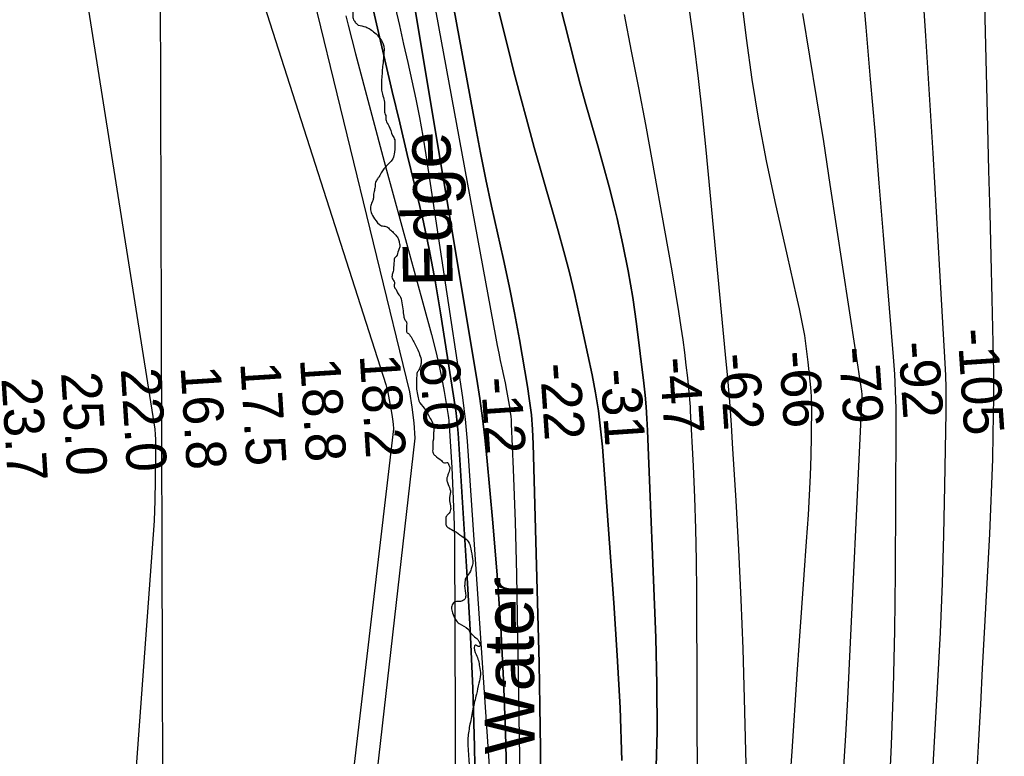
# Model space of a CAD drawing. Extents: x 3392644 to 3430565, y 576657 to 602123.
# Drawn here: x 3401788 to 3403434, y 588397 to 589627 of the extents above; entities that cross this region are included whole.
import ezdxf

# ---------------------------------------------------------------- set-up
doc = ezdxf.new("R2010")
doc.units = 0
for name, color, linetype in [('V-GRID-MAJR', 7, 'Continuous'), ('V-RIVR-EDGE', 7, 'Continuous'), ('V-RIVR-IDEN', 7, 'Continuous'), ('V-RIVR-RANG', 7, 'Continuous'), ('V-TOPO-DPTH', 7, 'Continuous'), ('V-TOPO-MAJR', 7, 'Continuous'), ('V-TOPO-MINR', 7, 'Continuous'), ('V-TOPO-WATR', 7, 'Continuous')]:
    doc.layers.add(name, color=color, linetype=linetype)

msp = doc.modelspace()

# ---------------------------------------------------------------- linework, layer by layer
at = {"layer": 'V-GRID-MAJR'}
msp.add_spline([(3402048.7, 582063.5), (3402028.4, 588122.7), (3402008.1, 594183.8), (3401987.8, 600244.9), (3401987.8, 600246.8)], degree=3, dxfattribs=at)
at = {"layer": 'V-RIVR-EDGE'}
for points in [[(3402225.6, 590211.5), (3402227.3, 590192.8), (3402229.7, 590176.3), (3402233.2, 590164.3), (3402236.4, 590151.2), (3402235.6, 590140), (3402236.3, 590123), (3402238, 590104.4), (3402239.7, 590087.8), (3402240.4, 590076.9), (3402241.1, 590060.7), (3402243.5, 590045.5), (3402245.6, 590032.1), (3402251.9, 590012.4), (3402259.9, 589993.3), (3402277.1, 589951), (3402284.5, 589928.8), (3402288.6, 589913.2), (3402293.5, 589897.4), (3402297.4, 589878.7), (3402301.2, 589857.2), (3402304.3, 589837.4), (3402303.2, 589822.7), (3402304.6, 589810), (3402308.1, 589790.6), (3402310.1, 589773.7), (3402314, 589761.3), (3402317.1, 589752.5), (3402320.3, 589740.9), (3402323.1, 589729.9), (3402325.2, 589722.5), (3402328.3, 589714.4), (3402332.5, 589705.2), (3402337.4, 589697.5), (3402337.4, 589693.9), (3402336.7, 589679.9), (3402336, 589670), (3402336, 589667.5), (3402336, 589664.7), (3402337.3, 589659.4), (3402338.7, 589655.2), (3402342.6, 589649.5), (3402345.1, 589645.3), (3402345.1, 589641.8), (3402345, 589634.7), (3402345, 589631.2), (3402346.4, 589627.3), (3402349.6, 589622.4), (3402353.8, 589618.5)], [(3402353.8, 589618.5), (3402366.5, 589615.3), (3402374.2, 589611.4), (3402381.6, 589605.7), (3402390, 589596.6), (3402395, 589588.4), (3402397.1, 589581.4), (3402397, 589574), (3402395.9, 589558.5), (3402394.5, 589546.5), (3402393.8, 589537), (3402393, 589512.3), (3402394.4, 589502.8), (3402397.5, 589492.2), (3402397.9, 589481.3), (3402398.2, 589473.2), (3402400.3, 589465.1), (3402400.6, 589459.1), (3402405.2, 589450.3), (3402411.5, 589434.1), (3402415, 589426.7), (3402415.3, 589418.2), (3402414.2, 589403), (3402410.3, 589392.8), (3402404, 589386.2), (3402398, 589379.5), (3402393.7, 589373.5), (3402389.1, 589365.4), (3402386.3, 589361.5), (3402383.1, 589355.6), (3402382.4, 589350.3), (3402381, 589342.2), (3402379.5, 589334.1), (3402379.2, 589328.4), (3402377.4, 589322.8), (3402375.6, 589318.9), (3402374.6, 589314.7), (3402375.6, 589305.5), (3402381.5, 589295), (3402392.8, 589283.3), (3402397, 589282.6), (3402403, 589280.8), (3402405.8, 589278.3), (3402411.1, 589273.4), (3402416.7, 589267.4), (3402420.9, 589261.7), (3402422.7, 589255), (3402423.4, 589248), (3402421.2, 589242), (3402417.7, 589232.1), (3402414.9, 589229.3), (3402414.1, 589225.8), (3402413.4, 589216.6), (3402412.3, 589206.8), (3402410.6, 589199.7), (3402410.6, 589195.9), (3402414.1, 589190.2), (3402414.8, 589187.4), (3402414, 589181.8), (3402417.2, 589176.5), (3402419.7, 589171.2), (3402424.6, 589164.1), (3402427.4, 589151.4), (3402429.4, 589137.7), (3402430.1, 589132.4), (3402432.2, 589126), (3402435, 589121.5), (3402435, 589116.9), (3402434.7, 589109.1), (3402434.6, 589106.3), (3402437.8, 589103.1), (3402443.4, 589095.4), (3402452.5, 589078.4), (3402456.7, 589068.2), (3402459.2, 589056.9), (3402458.5, 589050.6), (3402455.3, 589042.5), (3402452.8, 589038.2), (3402451.7, 589029.8), (3402451.3, 589013.2), (3402453.1, 589001.2), (3402455.5, 588991), (3402464.3, 588978.3), (3402474.5, 588961.4), (3402479.4, 588951.5), (3402480.4, 588942.7), (3402480, 588936), (3402480, 588928.6), (3402479.3, 588925.1), (3402478.9, 588923.3), (3402478.6, 588919.8), (3402478.6, 588911.7), (3402479.2, 588903.2), (3402482.4, 588899.3), (3402493, 588890.9), (3402500, 588887), (3402503.5, 588887.7), (3402504.9, 588884.8), (3402507, 588880.2), (3402506.7, 588875.3), (3402503.8, 588866.9), (3402502.4, 588862.3), (3402502.4, 588857.4), (3402504.1, 588851), (3402508, 588840.4), (3402507.6, 588834.4), (3402506.9, 588832), (3402506.5, 588826.7), (3402508.3, 588815.1), (3402507.9, 588807), (3402505.8, 588803.1), (3402501.9, 588798.9), (3402500.5, 588796), (3402500.5, 588789), (3402501.1, 588783), (3402505.4, 588778.4), (3402514.9, 588773.1), (3402527.2, 588764.6), (3402536.3, 588757.9), (3402541.2, 588748), (3402544.4, 588730.7), (3402545, 588716.3), (3402544, 588713.5), (3402541.5, 588706.4), (3402534.4, 588695.9), (3402533, 588692.7), (3402532.3, 588688.1), (3402531.9, 588681.8), (3402533.6, 588664.9), (3402532.2, 588659.2), (3402530.1, 588657.8), (3402526.6, 588656.1), (3402520.9, 588655.7), (3402516, 588655.1), (3402511, 588650.1), (3402510, 588645.9), (3402511.7, 588636.7), (3402516.6, 588625.5), (3402522.9, 588618.7), (3402537.7, 588609.5), (3402541.6, 588603.2), (3402555.3, 588590.1), (3402557.7, 588583.4), (3402557.4, 588581), (3402555.3, 588580.3), (3402549.3, 588582.7), (3402548.6, 588581.7), (3402551.4, 588566.9), (3402556.9, 588546.8), (3402558.3, 588533.4), (3402555.8, 588519.3), (3402551.5, 588500.6), (3402545.8, 588476.3), (3402540.8, 588450.6), (3402537.3, 588427.7), (3402537.6, 588409.4), (3402540.3, 588376.6), (3402543.8, 588353.7), (3402545.9, 588337.8), (3402545.8, 588329.4), (3402544.4, 588315.6), (3402545.1, 588298), (3402545.7, 588281.1), (3402547.8, 588258.2), (3402551.9, 588229.3), (3402553.3, 588209.6), (3402552.9, 588188.4), (3402549.7, 588179.6), (3402546.1, 588169.4), (3402540.8, 588162.7), (3402533.8, 588150.8), (3402529.9, 588147.3), (3402526, 588140.9), (3402522.4, 588130), (3402519.2, 588120.1), (3402514.6, 588114.5), (3402506.2, 588106.8), (3402488.2, 588098.7), (3402471.9, 588090), (3402440.6, 588078.8), (3402422.2, 588075.3), (3402415.9, 588073.5), (3402398.2, 588064.8), (3402386.6, 588057), (3402370.4, 588047.9), (3402356.2, 588038.8), (3402348.1, 588034.6), (3402339.3, 588028.6), (3402333.3, 588024.1), (3402331.2, 588019.5), (3402331.5, 588014.9), (3402332.5, 588000.1), (3402332.5, 587991.6), (3402329, 587984.2), (3402322.6, 587974.4), (3402313.8, 587963.8), (3402308.8, 587958.9), (3402306, 587955.8), (3402304.2, 587950.1), (3402303.9, 587945.2), (3402305.2, 587935), (3402309.8, 587926.5), (3402319.3, 587917), (3402329.5, 587902.8), (3402335.8, 587884.2), (3402342.1, 587862.3), (3402345.9, 587842.2), (3402353.9, 587818.9), (3402358.5, 587809.4), (3402369.7, 587790.7), (3402379.9, 587780.1), (3402387.3, 587770.2), (3402388.7, 587763.5), (3402389, 587754.3), (3402390, 587743.4), (3402392.1, 587734.6), (3402398.5, 587723), (3402409, 587712), (3402420.3, 587707.4), (3402430.5, 587701.4), (3402445.2, 587685.8), (3402460.3, 587664), (3402481.8, 587636.8), (3402490.5, 587630.1), (3402492.3, 587626.5), (3402492.3, 587618.1), (3402491.9, 587599.4), (3402491.9, 587595.5), (3402491.9, 587590.2), (3402495, 587583.2), (3402501.3, 587577.2), (3402510.1, 587565.9), (3402515.7, 587553.9), (3402518.5, 587544), (3402518.5, 587531.7), (3402519.5, 587529.2), (3402523.4, 587523.2), (3402528.3, 587508.7), (3402533.9, 587486.5), (3402537.7, 587460.8), (3402539, 587431.9), (3402536.9, 587417.1), (3402532.3, 587408.7), (3402524.9, 587399.9), (3402517.4, 587390), (3402513.5, 587381.2), (3402507.9, 587372.1), (3402500.8, 587364), (3402488.5, 587355.2), (3402476.1, 587351), (3402462.7, 587348.6), (3402451.8, 587349.7), (3402445.5, 587351.1), (3402438.1, 587349.3), (3402430.3, 587346.2), (3402425.3, 587341.6), (3402421.5, 587336), (3402417.9, 587328.3), (3402416.8, 587321.6), (3402415.8, 587316.6), (3402410.8, 587307.1), (3402403.4, 587294.8), (3402392.4, 587282.5), (3402386.8, 587277.9), (3402383.3, 587275.8), (3402380.1, 587272), (3402375.1, 587262.1), (3402369.1, 587248.7), (3402364.1, 587236.8), (3402356.7, 587226.2), (3402346.5, 587216.7), (3402334.8, 587207.6), (3402327.4, 587198.8), (3402315.7, 587187.2), (3402307.3, 587180.5), (3402292.4, 587173.2), (3402276.6, 587166.9), (3402266.7, 587162.7), (3402262.1, 587159.5), (3402256.4, 587151.8), (3402246.9, 587135.2), (3402240.5, 587123.3), (3402226.7, 587110.6), (3402209.8, 587100.1), (3402205.6, 587099.7), (3402201, 587104.7), (3402196.4, 587107.5), (3402189.7, 587104), (3402180.9, 587103.3), (3402167.9, 587099.5), (3402150.6, 587088.2), (3402138.2, 587077.3), (3402130.8, 587067.9), (3402126.9, 587059.8), (3402123.7, 587052.4), (3402122.3, 587043.6), (3402124, 587031.2), (3402118.7, 587026.3)]]:
    msp.add_spline(points, degree=3, dxfattribs=at)
at = {"layer": 'V-TOPO-DPTH'}
for points in [[(3401983.2, 590968.7), (3401990.2, 590884.7), (3401999.5, 590800.9), (3402010.4, 590717.3), (3402030.4, 590579.2), (3402032.7, 590564.7), (3402035.3, 590550.4), (3402268.2, 589718.4), (3402274.5, 589684.3), (3402439.7, 589005.6), (3402443.8, 588980), (3402447, 588954.2), (3402448.8, 588928.3), (3402356.8, 588119.6)], [(3402608.2, 588137.8), (3402600, 588437), (3402596.8, 588524.7), (3402592.4, 588612.2), (3402586.4, 588699.7), (3402579.2, 588787.1), (3402569.2, 588896), (3402565.8, 588928.9), (3402561.9, 588961.7), (3402557.3, 588994.5), (3402552.2, 589027.1), (3402440, 589701.1)], [(3402608.2, 588137.8), (3402600, 588437), (3402596.8, 588524.7), (3402592.4, 588612.2), (3402586.4, 588699.7), (3402579.2, 588787.1), (3402569.2, 588896), (3402565.8, 588928.9), (3402561.9, 588961.7), (3402557.3, 588994.5), (3402552.2, 589027.1), (3402440, 589701.1)], [(3402504.2, 589698.5), (3402549.8, 589449.6), (3402558.3, 589404.9), (3402567.3, 589360.3), (3402576.9, 589315.9), (3402587, 589271.5), (3402597, 589227.1), (3402606.5, 589182.6), (3402615.2, 589138), (3402623.4, 589093.2), (3402636.9, 589014.9), (3402640.5, 588991), (3402643.4, 588967.1), (3402645.3, 588943), (3402646.4, 588918.9), (3402656.3, 588552.8), (3402657.8, 588481.1), (3402658.7, 588409.4), (3402658.5, 588337.7)], [(3402658.5, 588337.7), (3402658.7, 588409.4), (3402657.8, 588481.1), (3402656.3, 588552.8), (3402646.4, 588918.9), (3402645.3, 588943), (3402643.4, 588967.1), (3402640.5, 588991), (3402636.9, 589014.9), (3402623.4, 589093.2), (3402615.2, 589138), (3402606.5, 589182.6), (3402597, 589227.1), (3402587, 589271.5), (3402576.9, 589315.9), (3402567.3, 589360.3), (3402558.3, 589404.9), (3402549.8, 589449.6), (3402504.2, 589698.5)], [(3402578.7, 589684), (3402604.4, 589579.5), (3402614.3, 589540.2), (3402624.4, 589500.9), (3402635, 589461.7), (3402645.7, 589422.5), (3402648.1, 589414.1), (3402658, 589379.3), (3402667.9, 589344.4), (3402677.9, 589309.6), (3402688, 589274.8), (3402697.8, 589240), (3402707.1, 589205), (3402715.5, 589169.8), (3402723.5, 589134.4), (3402744.8, 589034.2), (3402750.5, 589004.3), (3402755.4, 588974.3), (3402759.1, 588944.2), (3402762, 588913.9), (3402781.4, 588653.2), (3402787, 588565.5), (3402791.6, 588477.8), (3402794.5, 588390.1)], [(3402794.5, 588390.1), (3402791.6, 588477.8), (3402787, 588565.5), (3402781.4, 588653.2), (3402762, 588913.9), (3402759.1, 588944.2), (3402755.4, 588974.3), (3402750.5, 589004.3), (3402744.8, 589034.2), (3402723.5, 589134.4), (3402715.5, 589169.8), (3402707.1, 589205), (3402697.8, 589240), (3402688, 589274.8), (3402677.9, 589309.6), (3402667.9, 589344.4), (3402658, 589379.3), (3402648.1, 589414.1), (3402645.7, 589422.5), (3402635, 589461.7), (3402624.4, 589500.9), (3402614.3, 589540.2), (3402604.4, 589579.5), (3402578.7, 589684)], [(3402683.4, 589684.1), (3402706.9, 589589.1), (3402715.8, 589554.5), (3402724.9, 589520), (3402734.6, 589485.6), (3402744.6, 589451.3), (3402754.5, 589417), (3402764.2, 589382.6), (3402773.3, 589348), (3402782.1, 589313.4), (3402786.5, 589295.6), (3402796.5, 589251.8), (3402805.4, 589207.9), (3402812.7, 589163.6), (3402819, 589119.2), (3402831.1, 589020.2), (3402833.3, 589000.5), (3402835.1, 588980.7), (3402836.5, 588961), (3402837.5, 588941.2), (3402851.2, 588595), (3402853.1, 588516.8), (3402853.4, 588438.6), (3402851.2, 588360.4)], [(3402683.4, 589684.1), (3402706.9, 589589.1), (3402715.8, 589554.5), (3402724.9, 589520), (3402734.6, 589485.6), (3402744.6, 589451.3), (3402754.5, 589417), (3402764.2, 589382.6), (3402773.3, 589348), (3402782.1, 589313.4), (3402786.5, 589295.6), (3402796.5, 589251.8), (3402805.4, 589207.9), (3402812.7, 589163.6), (3402819, 589119.2), (3402831.1, 589020.2), (3402833.3, 589000.5), (3402835.1, 588980.7), (3402836.5, 588961), (3402837.5, 588941.2), (3402851.2, 588595), (3402853.1, 588516.8), (3402853.4, 588438.6), (3402851.2, 588360.4)], [(3402372.2, 589673.9), (3402398.5, 589560.4), (3402410.9, 589507.7), (3402423.4, 589455), (3402436.1, 589402.4), (3402448.9, 589349.8), (3402461.2, 589297.2), (3402472.5, 589244.3), (3402482.5, 589191.1), (3402491.6, 589137.8), (3402516.1, 588981.2), (3402517.6, 588970.1), (3402519, 588959), (3402520.1, 588947.8), (3402521, 588936.6), (3402535.8, 588705.3), (3402541.3, 588608.1), (3402545.7, 588510.9), (3402548.5, 588413.6), (3402550.2, 588316.3)], [(3402550.2, 588316.3), (3402548.5, 588413.6), (3402545.7, 588510.9), (3402541.3, 588608.1), (3402535.8, 588705.3), (3402521, 588936.6), (3402520.1, 588947.8), (3402519, 588959), (3402517.6, 588970.1), (3402516.1, 588981.2), (3402491.6, 589137.8), (3402482.5, 589191.1), (3402472.5, 589244.3), (3402461.2, 589297.2), (3402448.9, 589349.8), (3402436.1, 589402.4), (3402423.4, 589455), (3402410.9, 589507.7), (3402398.5, 589560.4), (3402372.2, 589673.9)]]:
    msp.add_lwpolyline(points, dxfattribs=at)
at = {"layer": 'V-TOPO-MAJR'}
for points in [[(3403291.8, 589751.2), (3403301.9, 589600.2), (3403308.2, 589502.3), (3403314.3, 589404.4), (3403320.1, 589306.4), (3403325.7, 589208.5), (3403334.3, 589053.7), (3403335.2, 589033.1), (3403335.8, 589012.5), (3403336, 588991.9), (3403335.9, 588971.3), (3403333.9, 588849), (3403332.2, 588767.2), (3403329.7, 588685.5), (3403326.3, 588603.8), (3403322.3, 588522.1), (3403301, 588139.4)], [(3402921.7, 588154.2), (3402920, 588671.6), (3402919.5, 588724.2), (3402918.4, 588776.7), (3402916.6, 588829.3), (3402914.2, 588881.8), (3402909.5, 588974.1), (3402909.1, 588980.5), (3402908.7, 588986.8), (3402908.1, 588993.2), (3402907.6, 588999.5), (3402904.6, 589029.3), (3402902.3, 589050.5), (3402899.8, 589071.7), (3402896.9, 589092.8), (3402893.7, 589113.9), (3402889.6, 589140), (3402884.1, 589174), (3402878.5, 589208.1), (3402872.6, 589242.1), (3402866.5, 589276), (3402845.7, 589390.6), (3402834.4, 589452.1), (3402822.9, 589513.6), (3402811, 589575), (3402798.9, 589636.3)]]:
    msp.add_lwpolyline(points, dxfattribs=at)
at = {"layer": 'V-TOPO-MINR'}
for points in [[(3401936.7, 591031.3), (3401939, 590935.1), (3401941.3, 590838.9), (3401943.4, 590742.7), (3401947.2, 590562.4), (3401947.4, 590554.2), (3401947.7, 590546), (3402173.1, 589731.3), (3402178.1, 589711.3), (3402400.1, 589018.2), (3402401.8, 589011.4), (3402403.4, 589004.5), (3402410.3, 588967.7), (3402411.5, 588959.9), (3402412.5, 588952), (3402413, 588944.1), (3402320.8, 588156.2)], [(3401983.2, 590968.7), (3401990.2, 590884.7), (3401999.5, 590800.9), (3402010.4, 590717.3), (3402030.4, 590579.2), (3402032.7, 590564.7), (3402035.3, 590550.4), (3402268.2, 589718.4), (3402274.5, 589684.3), (3402439.7, 589005.6), (3402443.8, 588980), (3402447, 588954.2), (3402448.8, 588928.3), (3402356.8, 588119.6)], [(3403397.6, 589767.5), (3403405.7, 589447.1), (3403407.5, 589375.5), (3403409.3, 589304), (3403411, 589232.4), (3403412.7, 589160.9), (3403415.6, 589038.7), (3403415.8, 589028.3), (3403415.9, 589017.8), (3403415.9, 589007.3), (3403415.8, 588996.8), (3403414.7, 588934.7), (3403413.8, 588893.1), (3403412.6, 588851.6), (3403410.9, 588810.1), (3403409, 588768.6), (3403400.2, 588603.4), (3403397, 588543.5), (3403393.7, 588483.6), (3403390.4, 588423.8), (3403387, 588363.9)], [(3403191.2, 589741.3), (3403202.2, 589615.2), (3403209.7, 589528.3), (3403217.1, 589441.4), (3403224.3, 589354.4), (3403231.5, 589267.5), (3403248, 589064.1), (3403250, 589035.5), (3403251.4, 589007), (3403252.2, 588978.5), (3403252.4, 588949.9), (3403251.3, 588702.8), (3403250.2, 588607.2), (3403248.1, 588511.6), (3403244.6, 588416), (3403240.1, 588320.5)], [(3402987.3, 589718.6), (3403002.4, 589596.4), (3403011.9, 589527.8), (3403022.8, 589459.4), (3403035.8, 589391.4), (3403050.2, 589323.6), (3403070.9, 589232.7), (3403075.9, 589210.6), (3403080.9, 589188.5), (3403085.9, 589166.4), (3403091, 589144.3), (3403095.5, 589122.2), (3403099.6, 589099.9), (3403102.8, 589077.5), (3403105.6, 589055.1), (3403109.8, 589013.3), (3403110.5, 589005.6), (3403111, 588997.8), (3403111.2, 588990), (3403111.3, 588982.2), (3403110.9, 588932), (3403110.3, 588899.1), (3403109.4, 588866.2), (3403107.8, 588833.4), (3403105.7, 588800.5), (3403102.5, 588755.6), (3403098.6, 588700.3), (3403094.7, 588644.9), (3403090.9, 588589.6), (3403087.2, 588534.3), (3403078.4, 588405.1), (3403075.2, 588358.7)], [(3402440, 589701.1), (3402552.2, 589027.1), (3402557.3, 588994.5), (3402561.9, 588961.7), (3402565.8, 588928.9), (3402569.2, 588896), (3402579.2, 588787.1), (3402586.4, 588699.7), (3402592.4, 588612.2), (3402596.8, 588524.7), (3402600, 588437), (3402608.2, 588137.8)], [(3402504.2, 589698.5), (3402549.8, 589449.6), (3402558.3, 589404.9), (3402567.3, 589360.3), (3402576.9, 589315.9), (3402587, 589271.5), (3402597, 589227.1), (3402606.5, 589182.6), (3402615.2, 589138), (3402623.4, 589093.2), (3402636.9, 589014.9), (3402640.5, 588991), (3402643.4, 588967.1), (3402645.3, 588943), (3402646.4, 588918.9), (3402656.3, 588552.8), (3402657.8, 588481.1), (3402658.7, 588409.4), (3402658.5, 588337.7)], [(3401896.3, 589689.8), (3402014.3, 588943.3), (3402014.7, 588934.6), (3402015.1, 588926), (3402015.2, 588917.4), (3402015.2, 588908.7), (3402014.7, 588858.2), (3402014, 588824.3), (3402012.8, 588790.4), (3401965.9, 588143.9)], [(3402578.7, 589684), (3402604.4, 589579.5), (3402614.3, 589540.2), (3402624.4, 589500.9), (3402635, 589461.7), (3402645.7, 589422.5), (3402648.1, 589414.1), (3402658, 589379.3), (3402667.9, 589344.4), (3402677.9, 589309.6), (3402688, 589274.8), (3402697.8, 589240), (3402707.1, 589205), (3402715.5, 589169.8), (3402723.5, 589134.4), (3402744.8, 589034.2), (3402750.5, 589004.3), (3402755.4, 588974.3), (3402759.1, 588944.2), (3402762, 588913.9), (3402781.4, 588653.2), (3402787, 588565.5), (3402791.6, 588477.8), (3402794.5, 588390.1)], [(3402851.2, 588360.4), (3402853.4, 588438.6), (3402853.1, 588516.8), (3402851.2, 588595), (3402837.5, 588941.2), (3402836.5, 588961), (3402835.1, 588980.7), (3402833.3, 589000.5), (3402831.1, 589020.2), (3402819, 589119.2), (3402812.7, 589163.6), (3402805.4, 589207.9), (3402796.5, 589251.8), (3402786.5, 589295.6), (3402782.1, 589313.4), (3402773.3, 589348), (3402764.2, 589382.6), (3402754.5, 589417), (3402744.6, 589451.3), (3402734.6, 589485.6), (3402724.9, 589520), (3402715.8, 589554.5), (3402706.9, 589589.1), (3402683.4, 589684.1)], [(3402479.3, 589665.2), (3402584, 589095.6), (3402586.4, 589083.1), (3402588.9, 589070.6), (3402591.5, 589058.1), (3402594.2, 589045.7), (3402596.9, 589033.2), (3402599.4, 589020.8), (3402601.8, 589008.3), (3402604.1, 588995.7), (3402607.3, 588977.3), (3402608.2, 588971.1), (3402609, 588964.9), (3402609.5, 588958.6), (3402609.9, 588952.4), (3402613.1, 588876.8), (3402614.9, 588832.8), (3402616.3, 588788.7), (3402617.5, 588744.6), (3402618.4, 588700.6), (3402627.7, 588157.7)], [(3402416, 589648.3), (3402422.9, 589617.6), (3402429.8, 589586.8), (3402436.8, 589556.2), (3402443.8, 589525.5), (3402450.4, 589494.7), (3402456.6, 589463.9), (3402462.1, 589432.9), (3402467.2, 589401.9), (3402528.1, 588996.1), (3402530.6, 588978), (3402532.8, 588959.9), (3402534.6, 588941.7), (3402536, 588923.5), (3402585.3, 588199.5)], [(3402906.8, 589647.7), (3402914.7, 589588.4), (3402922.1, 589529.1), (3402928.8, 589469.6), (3402934.8, 589410.1), (3402967.5, 589068), (3402971, 589028.7), (3402974.3, 588989.4), (3402977.1, 588950), (3402979.7, 588910.6), (3402984.9, 588824.3), (3402989.4, 588741.7), (3402993.4, 588659.1), (3402996.5, 588576.5), (3402999, 588493.8), (3403007.8, 588141.5)], [(3402333.2, 589634.1), (3402337, 589618.1), (3402349.3, 589570.4), (3402399.5, 589382.1), (3402476.5, 589101.6), (3402482.7, 589077.9), (3402488.3, 589054.2), (3402493.2, 589030.3), (3402497.5, 589006.3), (3402504.1, 588966.4), (3402504.7, 588962.3), (3402505.3, 588958.1), (3402505.7, 588953.9), (3402506, 588949.7), (3402510.3, 588879.2), (3402512.4, 588839.8), (3402514, 588800.3), (3402514.9, 588760.8), (3402517, 588145.3)], [(3403096.6, 589637.7), (3403108.4, 589566.4), (3403120.1, 589495.1), (3403131.4, 589423.8), (3403142.4, 589352.3), (3403195.3, 589006.8), (3403195.3, 589006.4), (3403195.7, 589001.9), (3403195.6, 588999), (3403195.5, 588998.3), (3403171.6, 588492.8), (3403168.3, 588431.8), (3403164.5, 588370.9)]]:
    msp.add_lwpolyline(points, dxfattribs=at)
at = {"layer": 'V-TOPO-WATR'}
msp.add_lwpolyline([(3402372.2, 589673.9), (3402398.5, 589560.4), (3402410.9, 589507.7), (3402423.4, 589455), (3402436.1, 589402.4), (3402448.9, 589349.8), (3402461.2, 589297.2), (3402472.5, 589244.3), (3402482.5, 589191.1), (3402491.6, 589137.8), (3402516.1, 588981.2), (3402517.6, 588970.1), (3402519, 588959), (3402520.1, 588947.8), (3402521, 588936.6), (3402535.8, 588705.3), (3402541.3, 588608.1), (3402545.7, 588510.9), (3402548.5, 588413.6), (3402550.2, 588316.3)], dxfattribs=at)

# ---------------------------------------------------------------- texts
at = {"layer": 'V-RIVR-IDEN'}
for s, rotation, p in [('Edge', 90.9428, (3402512.1, 589182)), ('Water ', 90.5032, (3402649, 588401.1))]:
    msp.add_text(s, height=83, rotation=rotation, dxfattribs=at).set_placement(p)
at = {"layer": 'V-RIVR-RANG'}
for s, rotation, p in [('-105', 273.8894, (3403355.2, 589110.2)), ('-92', 273.8894, (3403256.5, 589088.4)), ('-66', 273.8894, (3403057.1, 589072.7)), ('-79', 273.8894, (3403156.8, 589079.5)), ('18.8', 273.6083, (3402256.6, 589060.9)), ('18.2', 273.6083, (3402356.4, 589067.4)), ('6.0', 273.8894, (3402456.4, 589062.4)), ('-47', 273.8894, (3402857.3, 589062.2)), ('-62', 273.8894, (3402957.1, 589068.8)), ('22.0', 273.6083, (3401957.1, 589044.1)), ('16.8', 273.6083, (3402057, 589047.8)), ('17.5', 273.6083, (3402156.8, 589054.3)), ('-22', 273.8894, (3402657.5, 589052.3)), ('-31', 273.8894, (3402758.4, 589042.8)), ('23.7', 273.6083, (3401757.7, 589028.2)), ('25.0', 273.6083, (3401857.3, 589037.6)), ('-12', 273.8894, (3402558.9, 589028.9))]:
    msp.add_text(s, height=67, rotation=rotation, dxfattribs=at).set_placement(p)

doc.saveas('drawing.dxf')
